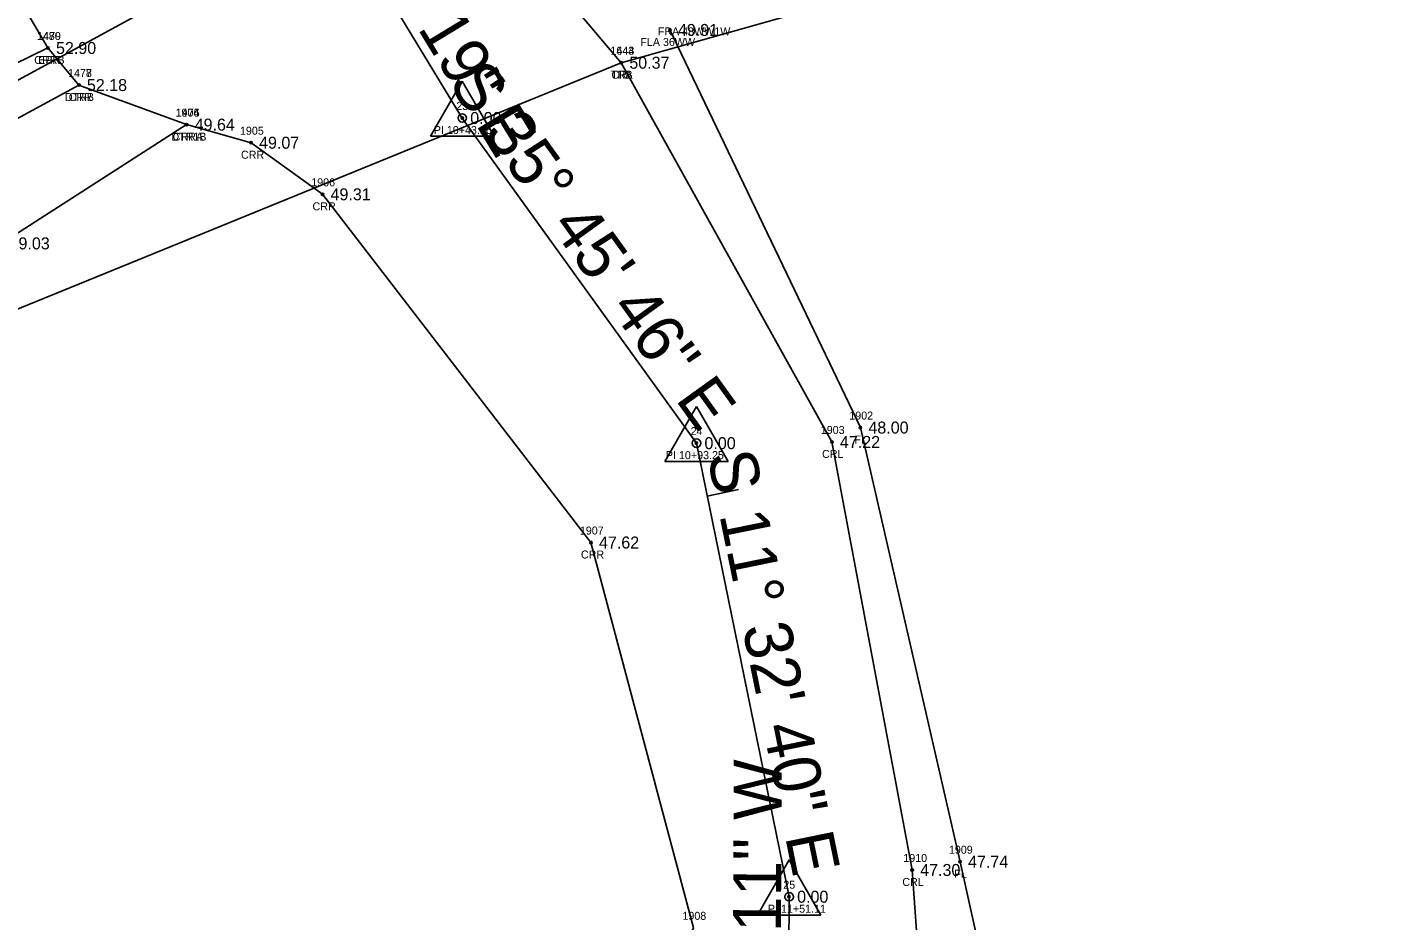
# Model space of a CAD drawing. Extents: x 2420113 to 2422887, y 845323 to 846653.
# Drawn here: x 2421748.2 to 2421918.2, y 845678.8 to 845790.5 of the extents above; entities that cross this region are included whole.
import ezdxf

# ---------------------------------------------------------------- set-up
doc = ezdxf.new("R2010")
doc.units = 0
for name, color, linetype in [('RD_EX_Fence_Other', 7, 'Continuous'), ('RD_EX_Fence_Other_txCode', 7, 'Continuous'), ('RD_EX_GuardRail', 7, 'Continuous'), ('RD_EX_H2O', 7, 'Continuous'), ('RD_EX_H2O_txCode', 7, 'Continuous'), ('RD_EX_Road', 7, 'Continuous'), ('RD_EX_Road_txCode', 7, 'Continuous'), ('RD_EX_TX_Fence_Other_ELEV', 7, 'Continuous'), ('RD_EX_TX_H2O_ELEV', 7, 'Continuous'), ('RD_EX_TX_Road_ELEV', 7, 'Continuous'), ('RD_EX_TX_VEG_ELEV', 7, 'Continuous'), ('RD_EX_VEG', 7, 'Continuous'), ('RD_EX_VEG_txCode', 7, 'Continuous'), ('RD_HC_Cl', 7, 'Continuous'), ('RD_HC_Data', 7, 'Continuous'), ('RD_HC_Data_Tic', 7, 'Continuous'), ('RD_HC_Survey_ELEV', 7, 'Continuous'), ('RD_HC_txCode', 7, 'Continuous'), ('RD_SMD_Locator', 7, 'Continuous')]:
    doc.layers.add(name, color=color, linetype=linetype)

msp = doc.modelspace()

# ---------------------------------------------------------------- linework, layer by layer
at = {"layer": 'RD_EX_Fence_Other'}
msp.add_lwpolyline([(2421828.48, 845790.12), (2421852.28, 845740.43), (2421864.73, 845686.16), (2421868.8, 845667.89)], dxfattribs=at)
at = {"layer": 'RD_EX_GuardRail'}
msp.add_lwpolyline([(2421700.48, 845761.64), (2421736.86, 845778.33), (2421765.25, 845793.79), (2421765.25, 845793.79), (2421804.57, 845814.88), (2421817.05, 845820.87), (2421867.07, 845850.23)], dxfattribs=at)
at = {"layer": 'RD_EX_H2O'}
for points in [[(2421810.77, 845819.82), (2421810.76, 845810.56), (2421816.9, 845792.5), (2421822.4, 845786.03), (2421848.72, 845738.63), (2421858.75, 845685.13), (2421860.35, 845662.88), (2421845.9, 845650.47), (2421833.11, 845629.75), (2421840.79, 845614.06), (2421848.44, 845579.41), (2421832.04, 845554.52), (2421837.19, 845498.45), (2421811.62, 845484.13), (2421811.72, 845469.11), (2421841.99, 845438.03), (2421875.97, 845424.56), (2421900.41, 845383.13), (2421915.29, 845367.51)], [(2421768.08, 845778.29), (2421754.61, 845783.24), (2421750.75, 845787.87)], [(2421462.85, 845683.51), (2421560.11, 845709.79), (2421615.97, 845726.65), (2421668.49, 845745.18), (2421738.54, 845774.52), (2421754.61, 845783.24)], [(2421462.85, 845683.51), (2421463.34, 845677.36), (2421472.12, 845675.5), (2421563.69, 845698.26), (2421619.71, 845715.72), (2421671.24, 845734.85), (2421744.95, 845763.45), (2421768.08, 845778.29)], [(2421768.08, 845778.29), (2421776.13, 845776.03), (2421785.06, 845769.58), (2421818.61, 845726.06), (2421831.42, 845677.9), (2421825.05, 845663.86), (2421816.1, 845638.14), (2421820.64, 845608.52), (2421828.09, 845585.14), (2421817.9, 845575.21), (2421808.75, 845549.61), (2421816.7, 845511.81), (2421785.75, 845489.97), (2421789.04, 845473.23), (2421801.09, 845449.66), (2421834.75, 845418.44), (2421870.95, 845402.12), (2421876.24, 845387.07), (2421866.97, 845385.32), (2421844.91, 845376.57), (2421842.84, 845344.63)]]:
    msp.add_lwpolyline(points, dxfattribs=at)
at = {"layer": 'RD_EX_Road'}
msp.add_lwpolyline([(2420388.28, 845680.39), (2420441.29, 845692.04), (2420492.62, 845700.7), (2420553.92, 845707.41), (2420607.69, 845710.85), (2420682.38, 845711.26), (2420749.44, 845707.27), (2420795.12, 845703.44), (2420900.28, 845693.42), (2421017.17, 845682.19), (2421113.9, 845672.97), (2421174.87, 845668.16), (2421234.59, 845666.13), (2421293, 845667.25), (2421351.24, 845671.5), (2421419.82, 845681.17), (2421463.19, 845688.63), (2421558.82, 845713.18), (2421614.57, 845730.45), (2421670.73, 845751.42), (2421735.61, 845780.5), (2421750.75, 845787.87), (2421744.67, 845798.22), (2421739.21, 845808.11)], dxfattribs=at)
at = {"layer": 'RD_EX_VEG'}
msp.add_lwpolyline([(2421514.28, 845601.29), (2421515.71, 845632.65), (2421540.03, 845670.81), (2421822.4, 845786.03), (2421822.4, 845786.03), (2421928.63, 845815.98), (2422026.48, 845905.33), (2422114.13, 845963.57), (2422135.16, 845938.99)], dxfattribs=at)
at = {"layer": 'RD_HC_Cl'}
for p, q in [((2421780.13, 845816.03), (2421802.52, 845779.12)), ((2421802.52, 845779.12), (2421831.79, 845738.48)), ((2421831.79, 845738.48), (2421843.37, 845681.79)), ((2421843.37, 845681.79), (2421843.25, 845658.16))]:
    msp.add_line(p, q, dxfattribs=at)
msp.add_arc((2421235.71, 846823.95), 1145.56, 264.46476, 308.21213, dxfattribs=at)
at = {"layer": 'RD_HC_Data'}
for p, q in [((2421798.55, 845776.83), (2421802.52, 845783.71)), ((2421802.52, 845783.71), (2421806.49, 845776.83)), ((2421798.55, 845776.83), (2421806.49, 845776.83)), ((2421827.82, 845736.19), (2421831.79, 845743.07)), ((2421831.79, 845743.07), (2421835.76, 845736.19)), ((2421827.82, 845736.19), (2421835.76, 845736.19)), ((2421839.4, 845679.5), (2421843.37, 845686.38)), ((2421843.37, 845686.38), (2421847.34, 845679.5)), ((2421839.4, 845679.5), (2421847.34, 845679.5))]:
    msp.add_line(p, q, dxfattribs=at)
for centre in [(2421802.52, 845779.12), (2421831.79, 845738.48), (2421843.37, 845681.79)]:
    msp.add_circle(centre, 0.529, dxfattribs=at)
at = {"layer": 'RD_HC_Data_Tic'}
msp.add_line((2421833.14, 845731.87), (2421837.06, 845732.67), dxfattribs=at)
at = {"layer": 'RD_SMD_Locator'}
for centre in [(2421828.48, 845790.12), (2421750.75, 845787.87), (2421750.75, 845787.87), (2421822.4, 845786.03), (2421822.4, 845786.03), (2421822.4, 845786.03), (2421754.61, 845783.24), (2421754.61, 845783.24), (2421768.08, 845778.29), (2421768.08, 845778.29), (2421768.08, 845778.29), (2421802.52, 845779.12), (2421776.13, 845776.03), (2421785.06, 845769.58), (2421852.28, 845740.43), (2421848.72, 845738.63), (2421831.79, 845738.48), (2421818.61, 845726.06), (2421864.73, 845686.16), (2421858.75, 845685.13), (2421843.37, 845681.79)]:
    msp.add_circle(centre, 0.15, dxfattribs=at)

# ---------------------------------------------------------------- texts
at = {"layer": 'RD_EX_Fence_Other_txCode'}
for s, p in [('FRA 48WW1W', (2421826.96, 845789.44)), ('FLA 36WW', (2421824.78, 845788.12)), ('1902', (2421850.89, 845741.43)), ('FL', (2421851.54, 845738.43)), ('1909', (2421863.34, 845687.16)), ('FL', (2421864, 845684.16))]:
    msp.add_text(s, height=1, dxfattribs=at).set_placement(p)
at = {"layer": 'RD_EX_H2O_txCode'}
for s, p in [('1479', (2421749.4, 845788.87)), ('1643', (2421821.03, 845787.03)), ('CRRB', (2421749.03, 845785.87)), ('1478', (2421753.26, 845784.24)), ('1477', (2421753.26, 845784.24)), ('CRL', (2421821.17, 845784.03)), ('DTRB', (2421752.86, 845781.24)), ('CRR', (2421753.35, 845781.24)), ('1904', (2421766.69, 845779.29)), ('1476', (2421766.71, 845779.29)), ('1475', (2421766.73, 845779.29)), ('1905', (2421774.74, 845777.03)), ('DTR1B', (2421766.17, 845776.29)), ('CRRA', (2421766.34, 845776.29)), ('CRRA', (2421766.34, 845776.29)), ('CRR', (2421774.87, 845774.03)), ('1906', (2421783.65, 845770.58)), ('CRR', (2421783.81, 845767.58)), ('1903', (2421847.33, 845739.63)), ('CRL', (2421847.49, 845736.63)), ('1907', (2421817.22, 845727.06)), ('CRR', (2421817.35, 845724.06)), ('1910', (2421857.64, 845686.13)), ('CRL', (2421857.52, 845683.13)), ('1908', (2421830.04, 845678.9))]:
    msp.add_text(s, height=1, dxfattribs=at).set_placement(p)
at = {"layer": 'RD_EX_Road_txCode'}
for s, p in [('1480', (2421749.36, 845788.87)), ('EPR', (2421749.52, 845785.87))]:
    msp.add_text(s, height=1, dxfattribs=at).set_placement(p)
at = {"layer": 'RD_EX_TX_Fence_Other_ELEV'}
for s, p in [('49.91', (2421829.48, 845789.37)), ('48.00', (2421853.28, 845739.68)), ('47.74', (2421865.73, 845685.41))]:
    msp.add_text(s, height=1.5, dxfattribs=at).set_placement(p)
at = {"layer": 'RD_EX_TX_H2O_ELEV'}
for s, p in [('52.90', (2421751.75, 845787.12)), ('50.37', (2421823.4, 845785.28)), ('52.18', (2421755.61, 845782.49)), ('52.18', (2421755.61, 845782.49)), ('49.64', (2421769.08, 845777.54)), ('49.64', (2421769.08, 845777.54)), ('49.64', (2421769.08, 845777.54)), ('49.07', (2421777.13, 845775.28)), ('49.31', (2421786.06, 845768.83)), ('49.03', (2421745.95, 845762.7)), ('47.22', (2421849.72, 845737.88)), ('47.62', (2421819.61, 845725.31)), ('47.30', (2421859.75, 845684.38))]:
    msp.add_text(s, height=1.5, dxfattribs=at).set_placement(p)
at = {"layer": 'RD_EX_TX_Road_ELEV'}
msp.add_text('52.90', height=1.5, dxfattribs=at).set_placement((2421751.75, 845787.12))
at = {"layer": 'RD_EX_TX_VEG_ELEV'}
msp.add_text('50.37', height=1.5, dxfattribs=at).set_placement((2421823.4, 845785.28))
msp.add_text('50.37', height=1.5, dxfattribs=at).set_placement((2421823.4, 845785.28))
at = {"layer": 'RD_EX_VEG_txCode'}
for s, p in [('1644', (2421821.03, 845787.03)), ('1443', (2421821.05, 845787.03)), ('TRA', (2421821.11, 845784.03)), ('TRB', (2421821.13, 845784.03))]:
    msp.add_text(s, height=1, dxfattribs=at).set_placement(p)
at = {"layer": 'RD_HC_Data'}
for s, rotation, p in [('S 31%%d 14\' 19" E', 301.2387, (2421778.91, 845819.97)), ('S 35%%d 45\' 46" E', 305.7628, (2421800.64, 845783.44)), ('S 11%%d 32\' 40" E', 281.5446, (2421833.12, 845736.98)), ('S 0%%d 17\' 11" W', 89.7137, (2421842.2, 845647.19))]:
    msp.add_text(s, height=6, rotation=rotation, dxfattribs=at).set_placement(p)
at = {"layer": 'RD_HC_Survey_ELEV'}
for p in [(2421803.52, 845778.37), (2421832.79, 845737.73), (2421844.37, 845681.04)]:
    msp.add_text('0.00', height=1.5, dxfattribs=at).set_placement(p)
at = {"layer": 'RD_HC_txCode'}
for s, p in [('23', (2421801.78, 845780.12)), ('PI 10+43.16', (2421798.96, 845777.12)), ('24', (2421831.06, 845739.48)), ('PI 10+93.25', (2421827.97, 845736.48)), ('25', (2421842.64, 845682.79)), ('PI 11+51.11', (2421840.72, 845679.79))]:
    msp.add_text(s, height=1, dxfattribs=at).set_placement(p)

doc.saveas('drawing.dxf')
